// Mitsubishi GX Works2 project: FX3G_COM3_RD3A   PLC: FX3G

PROGRAM MAIN
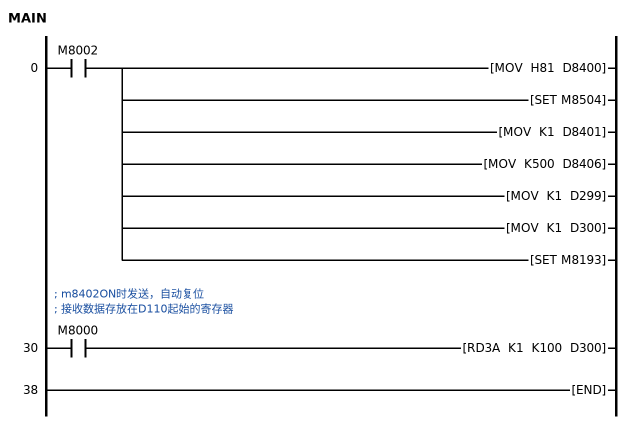
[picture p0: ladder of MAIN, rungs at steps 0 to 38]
0     LD      M8002
      MOV     H81 D8400
        [note] 通讯设定9600 8 N 1
      SET     M8504
      MOV     K1 D8401
        [note] 设置主站
      MOV     K500 D8406
        [note] 间隔周期数
      MOV     K1 D299
      MOV     K1 D300
      SET     M8193
        [note] on:其他协议协议off:编程口协议
; m8402ON时发送，自动复位
; 接收数据存放在D110起始的寄存器
30    LD      M8000
      RD3A    K1 K100 D300
38    END
END_PROGRAM

// device comments not shown above
D200  ; 写入数量，1个
D211  ; 转速
M2  ; 反转
M3  ; 停止
